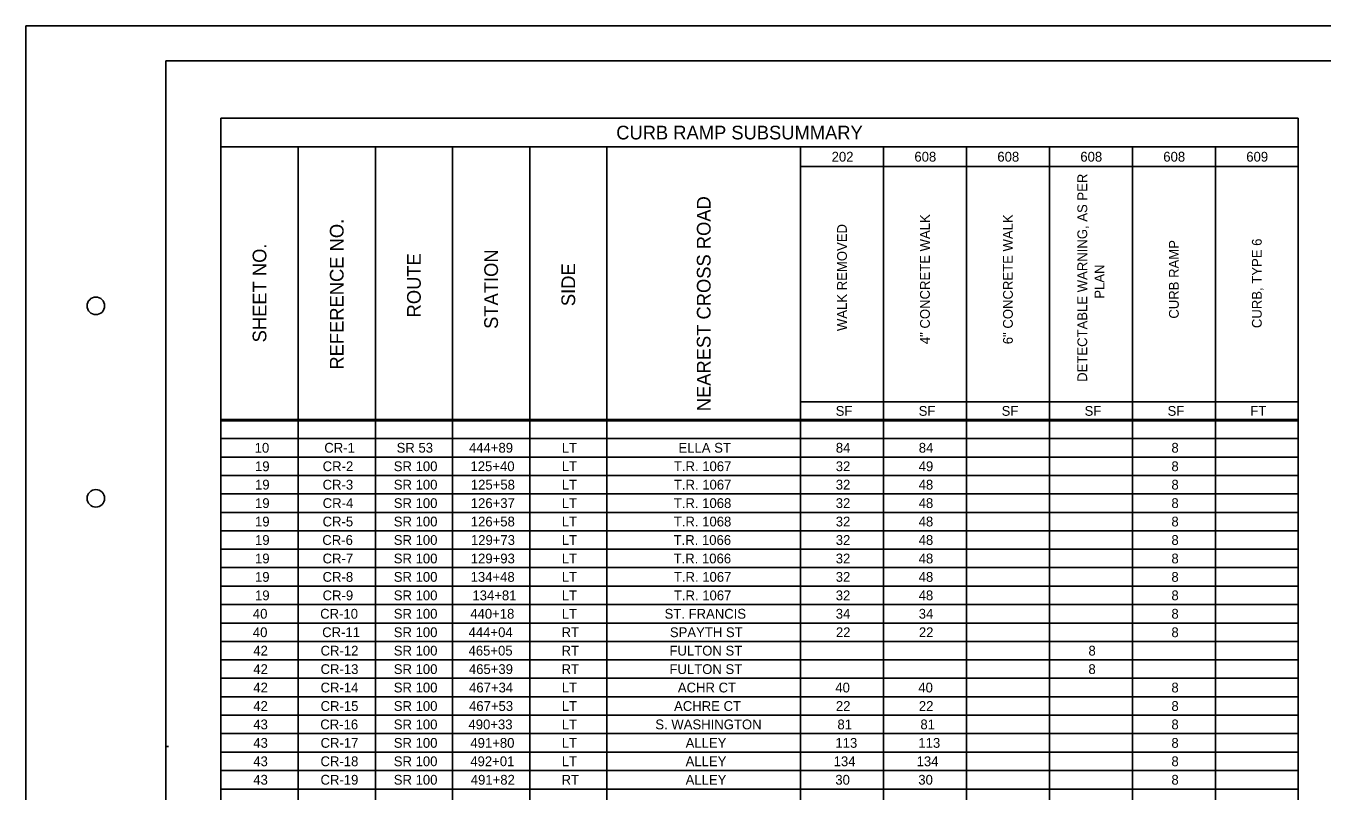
# Model space of a CAD drawing. Extents: x 44.3 to 78.3, y -12.9 to 9.1.
# Drawn here: x 44.28 to 62.81, y -1.8 to 9.13 of the extents above; entities that cross this region are included whole.
import ezdxf

# ---------------------------------------------------------------- set-up
doc = ezdxf.new("R2010")
doc.units = 0
for name, color, linetype in [('SH_Border', 7, 'Continuous'), ('SH_Cut_Line', 7, 'Continuous'), ('SH_Data', 7, 'Continuous'), ('SH_Text', 7, 'Continuous')]:
    doc.layers.add(name, color=color, linetype=linetype)

msp = doc.modelspace()

# ---------------------------------------------------------------- linework, layer by layer
at = {"layer": 'SH_Border'}
for p, q in [((46.279, 4.979), (46.279, 8.631)), ((46.279, -1.167), (46.316, -1.167))]:
    msp.add_line(p, q, dxfattribs=at)
msp.add_lwpolyline([(46.279, 8.631), (77.779, 8.631), (77.779, -12.369), (46.279, -12.369)], close=True, dxfattribs=at)
for centre in [(45.279, 5.131), (45.279, 2.381)]:
    msp.add_circle(centre, 0.125, dxfattribs=at)
at = {"layer": 'SH_Cut_Line'}
msp.add_lwpolyline([(44.279, -12.869), (78.279, -12.869), (78.279, 9.131), (44.279, 9.131)], close=True, dxfattribs=at)
at = {"layer": 'SH_Data'}
for p, q in [((47.066, 7.813), (62.466, 7.813)), ((47.066, 7.813), (47.066, 3.487)), ((62.466, 7.813), (62.466, 3.487)), ((47.066, 7.402), (62.466, 7.402)), ((48.17, 7.402), (48.17, 3.509)), ((49.274, 7.402), (49.274, 3.509)), ((50.377, 7.402), (50.377, 3.509)), ((51.481, 7.402), (51.481, 3.509)), ((52.584, 7.402), (52.584, 3.509)), ((55.351, 7.402), (55.351, 3.509)), ((56.537, 7.402), (56.537, 3.509)), ((57.723, 7.402), (57.723, 3.509)), ((58.909, 7.402), (58.909, 3.509)), ((60.095, 7.402), (60.095, 3.509)), ((61.281, 7.402), (61.281, 3.509)), ((55.351, 7.122), (62.466, 7.122)), ((55.351, 3.761), (62.466, 3.761)), ((47.066, 3.509), (62.466, 3.509)), ((47.066, 3.509), (47.066, -11.013)), ((47.066, 3.487), (62.466, 3.487)), ((48.17, 3.487), (48.17, -10.469)), ((49.274, 3.487), (49.274, -10.469)), ((50.377, 3.487), (50.377, -10.469)), ((51.481, 3.487), (51.481, -10.469)), ((52.584, 3.487), (52.584, -10.469)), ((55.351, 3.487), (55.351, -11.013)), ((56.537, 3.487), (56.537, -11.013)), ((57.723, 3.487), (57.723, -11.013)), ((58.909, 3.487), (58.909, -11.013)), ((60.095, 3.487), (60.095, -11.013)), ((61.281, 3.487), (61.281, -11.013)), ((62.466, 3.509), (62.466, -11.013)), ((47.066, 3.234), (62.466, 3.234)), ((47.066, 2.971), (62.466, 2.971)), ((47.066, 2.707), (62.466, 2.707)), ((47.066, 2.444), (62.466, 2.444)), ((47.066, 2.18), (62.466, 2.18)), ((47.066, 1.917), (62.466, 1.917)), ((47.066, 1.653), (62.466, 1.653)), ((47.066, 1.39), (62.466, 1.39)), ((47.066, 1.126), (62.466, 1.126)), ((47.066, 0.863), (62.466, 0.863)), ((47.066, 0.599), (62.466, 0.599)), ((47.066, 0.336), (62.466, 0.336)), ((47.066, 0.072), (62.466, 0.072)), ((47.066, -0.191), (62.466, -0.191)), ((47.066, -0.455), (62.466, -0.455)), ((47.066, -0.719), (62.466, -0.719)), ((47.066, -0.982), (62.466, -0.982)), ((47.066, -1.246), (62.466, -1.246)), ((47.066, -1.509), (62.466, -1.509)), ((47.066, -1.773), (62.466, -1.773))]:
    msp.add_line(p, q, dxfattribs=at)

# ---------------------------------------------------------------- texts
at = {"layer": 'SH_Text'}
for s, height, p in [('CURB RAMP SUBSUMMARY', 0.196, (52.717, 7.509)), ('202', 0.14, (55.796, 7.192)), ('608', 0.14, (56.979, 7.192)), ('608', 0.14, (58.165, 7.192)), ('608', 0.14, (59.351, 7.192)), ('608', 0.14, (60.537, 7.192)), ('609', 0.14, (61.723, 7.192)), ('SF', 0.14, (55.854, 3.56)), ('SF', 0.14, (57.04, 3.56)), ('SF', 0.14, (58.226, 3.56)), ('SF', 0.14, (59.412, 3.56)), ('SF', 0.14, (60.598, 3.56)), ('FT', 0.14, (61.78, 3.56)), ('10', 0.14, (47.549, 3.033)), ('CR-1', 0.14, (48.544, 3.033)), ('SR 53', 0.14, (49.578, 3.033)), ('444+89', 0.14, (50.612, 3.033)), ('LT', 0.14, (51.939, 3.033)), ('ELLA ST', 0.14, (53.607, 3.033)), ('84', 0.14, (55.856, 3.033)), ('84', 0.14, (57.042, 3.033)), ('8', 0.14, (60.653, 3.033)), ('19', 0.14, (47.554, 2.769)), ('CR-2', 0.14, (48.521, 2.769)), ('SR 100', 0.14, (49.537, 2.769)), ('125+40', 0.14, (50.634, 2.769)), ('LT', 0.14, (51.939, 2.769)), ('T.R. 1067', 0.14, (53.541, 2.769)), ('32', 0.14, (55.855, 2.769)), ('49', 0.14, (57.04, 2.769)), ('8', 0.14, (60.653, 2.769)), ('19', 0.14, (47.554, 2.506)), ('CR-3', 0.14, (48.52, 2.506)), ('SR 100', 0.14, (49.537, 2.506)), ('125+58', 0.14, (50.639, 2.506)), ('LT', 0.14, (51.939, 2.506)), ('T.R. 1067', 0.14, (53.541, 2.506)), ('32', 0.14, (55.855, 2.506)), ('48', 0.14, (57.04, 2.506)), ('8', 0.14, (60.653, 2.506)), ('19', 0.14, (47.554, 2.242)), ('CR-4', 0.14, (48.521, 2.242)), ('SR 100', 0.14, (49.537, 2.242)), ('126+37', 0.14, (50.638, 2.242)), ('LT', 0.14, (51.939, 2.242)), ('T.R. 1068', 0.14, (53.54, 2.242)), ('32', 0.14, (55.855, 2.242)), ('48', 0.14, (57.04, 2.242)), ('8', 0.14, (60.653, 2.242)), ('19', 0.14, (47.554, 1.979)), ('CR-5', 0.14, (48.52, 1.979)), ('SR 100', 0.14, (49.537, 1.979)), ('126+58', 0.14, (50.638, 1.979)), ('LT', 0.14, (51.939, 1.979)), ('T.R. 1068', 0.14, (53.54, 1.979)), ('32', 0.14, (55.855, 1.979)), ('48', 0.14, (57.04, 1.979)), ('8', 0.14, (60.653, 1.979)), ('19', 0.14, (47.554, 1.715)), ('CR-6', 0.14, (48.516, 1.715)), ('SR 100', 0.14, (49.537, 1.715)), ('129+73', 0.14, (50.64, 1.715)), ('LT', 0.14, (51.939, 1.715)), ('T.R. 1066', 0.14, (53.537, 1.715)), ('32', 0.14, (55.855, 1.715)), ('48', 0.14, (57.04, 1.715)), ('8', 0.14, (60.653, 1.715)), ('19', 0.14, (47.554, 1.451)), ('CR-7', 0.14, (48.52, 1.451)), ('SR 100', 0.14, (49.537, 1.451)), ('129+93', 0.14, (50.638, 1.451)), ('LT', 0.14, (51.939, 1.451)), ('T.R. 1066', 0.14, (53.537, 1.451)), ('32', 0.14, (55.855, 1.451)), ('48', 0.14, (57.04, 1.451)), ('8', 0.14, (60.653, 1.451)), ('19', 0.14, (47.554, 1.188)), ('CR-8', 0.14, (48.52, 1.188)), ('SR 100', 0.14, (49.537, 1.188)), ('134+48', 0.14, (50.636, 1.188)), ('LT', 0.14, (51.939, 1.188)), ('T.R. 1067', 0.14, (53.541, 1.188)), ('32', 0.14, (55.855, 1.188)), ('48', 0.14, (57.04, 1.188)), ('8', 0.14, (60.653, 1.188)), ('19', 0.14, (47.554, 0.924)), ('CR-9', 0.14, (48.52, 0.924)), ('SR 100', 0.14, (49.537, 0.924)), ('134+81', 0.14, (50.661, 0.924)), ('LT', 0.14, (51.939, 0.924)), ('T.R. 1067', 0.14, (53.541, 0.924)), ('32', 0.14, (55.855, 0.924)), ('48', 0.14, (57.04, 0.924)), ('8', 0.14, (60.653, 0.924)), ('40', 0.14, (47.523, 0.661)), ('CR-10', 0.14, (48.485, 0.661)), ('SR 100', 0.14, (49.537, 0.661)), ('440+18', 0.14, (50.631, 0.661)), ('LT', 0.14, (51.939, 0.661)), ('ST. FRANCIS', 0.14, (53.408, 0.661)), ('34', 0.14, (55.855, 0.661)), ('34', 0.14, (57.041, 0.661)), ('8', 0.14, (60.653, 0.661)), ('40', 0.14, (47.523, 0.397)), ('CR-11', 0.14, (48.514, 0.397)), ('SR 100', 0.14, (49.537, 0.397)), ('444+04', 0.14, (50.607, 0.397)), ('RT', 0.14, (51.936, 0.397)), ('SPAYTH ST', 0.14, (53.484, 0.397)), ('22', 0.14, (55.857, 0.397)), ('22', 0.14, (57.043, 0.397)), ('8', 0.14, (60.653, 0.397)), ('42', 0.14, (47.529, 0.134)), ('CR-12', 0.14, (48.491, 0.134)), ('SR 100', 0.14, (49.537, 0.134)), ('465+05', 0.14, (50.606, 0.134)), ('RT', 0.14, (51.936, 0.134)), ('FULTON ST', 0.14, (53.478, 0.134)), ('8', 0.14, (59.467, 0.134)), ('42', 0.14, (47.529, -0.13)), ('CR-13', 0.14, (48.491, -0.13)), ('SR 100', 0.14, (49.537, -0.13)), ('465+39', 0.14, (50.611, -0.13)), ('RT', 0.14, (51.936, -0.13)), ('FULTON ST', 0.14, (53.478, -0.13)), ('8', 0.14, (59.467, -0.13)), ('42', 0.14, (47.529, -0.393)), ('CR-14', 0.14, (48.491, -0.393)), ('SR 100', 0.14, (49.537, -0.393)), ('467+34', 0.14, (50.613, -0.393)), ('LT', 0.14, (51.939, -0.393)), ('ACHR CT', 0.14, (53.598, -0.393)), ('40', 0.14, (55.849, -0.393)), ('40', 0.14, (57.035, -0.393)), ('8', 0.14, (60.653, -0.393)), ('42', 0.14, (47.529, -0.657)), ('CR-15', 0.14, (48.491, -0.657)), ('SR 100', 0.14, (49.537, -0.657)), ('467+53', 0.14, (50.613, -0.657)), ('LT', 0.14, (51.939, -0.657)), ('ACHRE CT', 0.14, (53.544, -0.657)), ('22', 0.14, (55.857, -0.657)), ('22', 0.14, (57.043, -0.657)), ('8', 0.14, (60.653, -0.657)), ('43', 0.14, (47.529, -0.92)), ('CR-16', 0.14, (48.487, -0.92)), ('SR 100', 0.14, (49.537, -0.92)), ('490+33', 0.14, (50.605, -0.92)), ('LT', 0.14, (51.939, -0.92)), ('S. WASHINGTON', 0.14, (53.276, -0.92)), ('81', 0.14, (55.879, -0.92)), ('81', 0.14, (57.065, -0.92)), ('8', 0.14, (60.653, -0.92)), ('43', 0.14, (47.529, -1.184)), ('CR-17', 0.14, (48.491, -1.184)), ('SR 100', 0.14, (49.537, -1.184)), ('491+80', 0.14, (50.632, -1.184)), ('LT', 0.14, (51.939, -1.184)), ('ALLEY', 0.14, (53.709, -1.184)), ('113', 0.14, (55.85, -1.184)), ('113', 0.14, (57.036, -1.184)), ('8', 0.14, (60.653, -1.184)), ('43', 0.14, (47.529, -1.447)), ('CR-18', 0.14, (48.49, -1.447)), ('SR 100', 0.14, (49.537, -1.447)), ('492+01', 0.14, (50.631, -1.447)), ('LT', 0.14, (51.939, -1.447)), ('ALLEY', 0.14, (53.709, -1.447)), ('134', 0.14, (55.825, -1.447)), ('134', 0.14, (57.011, -1.447)), ('8', 0.14, (60.653, -1.447)), ('43', 0.14, (47.529, -1.711)), ('CR-19', 0.14, (48.49, -1.711)), ('SR 100', 0.14, (49.537, -1.711)), ('491+82', 0.14, (50.638, -1.711)), ('RT', 0.14, (51.936, -1.711)), ('ALLEY', 0.14, (53.709, -1.711)), ('30', 0.14, (55.849, -1.711)), ('30', 0.14, (57.035, -1.711)), ('8', 0.14, (60.653, -1.711))]:
    msp.add_text(s, height=height, dxfattribs=at).set_placement(p)
for s, height, p in [('DETECTABLE WARNING, AS PER', 0.14, (59.449, 4.045)), ('NEAREST CROSS ROAD', 0.196, (54.066, 3.625)), ('REFERENCE NO.', 0.196, (48.82, 4.22)), ('4" CONCRETE WALK', 0.14, (57.2, 4.584)), ('6" CONCRETE WALK', 0.14, (58.386, 4.583)), ('WALK REMOVED', 0.14, (56.014, 4.771)), ('SHEET NO.', 0.196, (47.716, 4.609)), ('CURB RAMP', 0.14, (60.758, 4.948)), ('CURB, TYPE 6', 0.14, (61.944, 4.813)), ('ROUTE', 0.196, (49.923, 4.966)), ('STATION', 0.196, (51.027, 4.802)), ('SIDE', 0.196, (52.13, 5.127)), ('PLAN', 0.14, (59.694, 5.233))]:
    msp.add_text(s, height=height, rotation=90, dxfattribs=at).set_placement(p)

doc.saveas('drawing.dxf')
